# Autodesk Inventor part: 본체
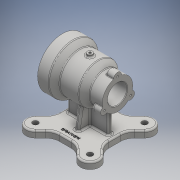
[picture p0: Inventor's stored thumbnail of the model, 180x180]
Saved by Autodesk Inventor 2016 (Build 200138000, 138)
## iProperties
Created: 2017-03
Part Number: 본체
Material: 일반
Document SubType Name: Modeling
Designer: USER
Density: 1 g/cm^3
Appearance: 기본값
Author: USER
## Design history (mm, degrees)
sketch "스케치1"
  geometry: L1 (0, 0)-(-100, 0); L2 (0, 35)-(-23, 35); L3 (-23, 35)-(-23, 26); L4 (-23, 26)-(-70, 26); L5 (-70, 26)-(-70, 17.5); L6 (-70, 17.5)-(-100, 17.5); L7 (-100, 17.5)-(-100, 27.5); L8 (-100, 27.5)-(-77, 27.5); L9 (-77, 27.5)-(-65, 36); L10 (-65, 36)-(-31, 36); L11 (-31, 36)-(-20, 45); L12 (-20, 45)-(0, 45); L13 (0, 45)-(0, 35); 2 further points
  constraints: 26 end point, 7 perpendicular, 2 horizontal, 2 midpoint, 2 parallel, 2 vertical alignment
  dimensions: "d0" = 35 diameter of L6 L1; "d1" = 100 distance between parallel lines of L7 L13; "d2" = 52 diameter of L4 L1; "d3" = 70 diameter of L2 L1; "d4" = 90 diameter of L12 L1; "d5" = 55 diameter of L8 L1; "d6" = 72 diameter of L10 L1; "d7" = 23 distance of L2.start L2.end; "d8" = 47 distance of L3.end L4.end; "d9" = 20 distance of L11.end L12.end; "d11" = 31 horizontal distance of L10.end L12.end; "d12" = 65 distance from line of L9.end L13; "d13" = 23 distance of L7.end L8.end
revolve "회전1" sketch "스케치1" stored, may be unused: angle "d14" = 90 deg
node "작업 평면1"
sketch "스케치2" dims "d26" = 140
  geometry: L1 (5, 45)-(95, 45); L2 (95, 45)-(95, -45); L3 (95, -45)-(5, -45); L4 (5, -45)-(5, 45); L5 (100, 27.5)-(100, -27.5) reference; L6 (50, 45)-(50, -45); L7 (29.042, 45)-(12.523, 61.518); L8 (5, 20.958)-(-11.518, 37.477); L9 (0.503, 49.497)-(99.487, -49.487); L10 (99.073, 49.073)-(0.078, -49.922); A1 r 17 centre (0.503, 49.497) between (12.523, 61.518) and (-11.518, 37.477); 5 further points
  constraints: 18 end point, 6 point on line, 4 midpoint, 2 coincident, 2 horizontal alignment, 2 parallel, 2 point on circle, 1 centre point, 1 horizontal, 1 perpendicular, 1 tangent, 1 vertical alignment, 4 other
  dimensions: "d16" = 90 distance of L1.start L1.end; "d17" = 90 distance of L1.end L2.end; "d18" = 50 distance from line of L6 point (0, 0); "d21" = 34 distance between parallel lines of L8 L7
extrude "돌출1" join sketch "스케치2" distance "d28" = 12; taper "d29" = 0 deg
extrude "돌출2" join sketch "스케치2" distance "d30" = 12; taper "d31" = 0 deg
node "작업 평면2"
sketch "스케치3"
  geometry: L1 (13, 4)-(87, 4); L2 (87, 4)-(87, -4); L3 (87, -4)-(13, -4); L4 (13, -4)-(13, 4); 3 further points
  constraints: 8 end point, 2 parallel, 1 horizontal, 1 horizontal alignment, 1 midpoint, 1 perpendicular
  dimensions: "d33" = 8 distance of L3.end L1.start; "d34" = 37 distance from line of L4 point (50, 45); "d35" = 37 distance from line of L2 point (50, 45)
extrude "돌출3" join sketch "스케치3" stored distance "d36" = 0; taper "d37" = 0 deg
sketch "스케치4"
  geometry: L1 (-37.477, -70)-(-20.958, -70) reference; L2 (37.477, -70)-(20.958, -70) reference; L3 (0, 0)-(0, -58.122); L4 (-16.238, -20.306)-(-25, -70); L5 (16.238, -20.306)-(25, -70); L6 (-4, -70)-(-4, -44.822) reference; L7 (20.958, -70)-(-20.958, -70) reference; L8 (4, -70)-(4, -44.822) reference; A1 r 26 centre (0, 0) between (-16.238, -20.306) and (16.238, -20.306) reference; 1 further point
  constraints: 6 end point, 2 point on circle, 2 point on line, 1 vertical
  dimensions: "d40" = 25 distance from line of L4.end L3; "d41" = 25 horizontal distance of L3.end L5.end; "d42" = 100 deg angle of L2 L5; "d43" = 100 deg angle of L1 L4
feature "리브1" dims "d44" = 1, "d45" = 8, "d46" = 0, "d47" = 0, "d48" = 1, "d49" = 1
feature "리브2" dims "d50" = 1, "d51" = 8, "d52" = 0, "d53" = 0, "d54" = 1, "d55" = 1
sketch "스케치5"
  geometry: C1 r 5 at (0.503, 49.497); C2 r 5 at (99.497, 49.497); C3 r 5 at (99.497, -49.497); C4 r 5 at (0.503, -49.497); A1 r 17 centre (0.503, 49.497) between (12.523, 61.518) and (-11.518, 37.477) reference; A2 r 17 centre (99.497, 49.497) between (111.518, 37.477) and (87.477, 61.518) reference; A3 r 17 centre (99.497, -49.497) between (87.477, -61.518) and (111.518, -37.477) reference; A4 r 17 centre (0.503, -49.497) between (-11.518, -37.477) and (12.523, -61.518) reference; 1 further point
  constraints: 4 centre point, 3 concentric, 3 equal radius, 1 coincident
  dimensions: "d57" = 10 diameter of C1
extrude "돌출4" cut sketch "스케치5" stored distance "d58" = 0; taper "d59" = 0 deg
node "작업 평면4"
sketch "스케치6"
  geometry: L1 (0, 45)-(0, -45) reference; C1 r 5 at (50, 0); 1 further point
  constraints: 1 centre point, 1 horizontal alignment
  dimensions: "d62" = 10 diameter of C1; "d63" = 50 distance from line of L1 C1.centre
extrude "돌출5" join sketch "스케치6" stored distance "d64" = 15; taper "d65" = 0 deg
sketch "스케치7"
  geometry: C1 r 5 at (0, 0) reference; 2 further points
  constraints: 1 coincident
hole "구멍1" sketch "스케치7" at (0, 0) diameter "d66" = 4.134; stored, may be unused: countersink angle "d70" = 90 deg, drill point angle "d72" = 118 deg; dims "d67" = 10, "d68" = 4, "d69" = 2, "d71" = 14.2
sketch "스케치8"
  geometry: A1 r 27.5 centre (0, 0) between (-27.5, 0) and (-26.609, -6.943) reference; A2 r 7 centre (-27.5, 0) between (-26.609, 6.943) and (-26.609, -6.943); A3 r 27.5 centre (0, 0) between (27.208, 4) and (27.208, -4) reference; 2 further points
  constraints: 6 point on circle, 1 centre point, 1 coincident
  dimensions: "d73" = 7 radius of A2
extrude "돌출6" join sketch "스케치8" distance "d76" = 15; taper "d77" = 0 deg
fillet "모깎기1" dims "d78" = 3
fillet "모깎기2" dims "d79" = 1
sketch "스케치9"
  geometry: A1 r 7 centre (0, 0) between (0.127, 6.999) and (0.127, -6.999) reference; 2 further points
  constraints: 1 coincident
hole "구멍2" sketch "스케치9" at (0, 0) diameter "d83" = 3.242; stored, may be unused: countersink angle "d87" = 90 deg, drill point angle "d89" = 118 deg; dims "d84" = 9, "d85" = 4, "d86" = 2, "d88" = 11
sketch "스케치10" dims "d93" = 80
  geometry: 3 further points
  constraints: 2 horizontal alignment, 1 coincident, 2 other
hole "구멍3" sketch "스케치10" at (40, 0) diameter "d94" = 3.242; stored, may be unused: countersink angle "d98" = 90 deg, drill point angle "d100" = 118 deg; dims "d95" = 9, "d96" = 4, "d97" = 2, "d99" = 11
chamfer "모따기1" distance "d104" = 1; stored, may be unused: second distance "d105" = 2, angle "d106" = 45 deg
fillet "모깎기3" dims "d107" = 3
fillet "모깎기4" dims "d108" = 3
fillet "모깎기5" dims "d109" = 3
fillet "모깎기6" dims "d110" = 3
fillet "모깎기7" dims "d111" = 3
fillet "모깎기8" dims "d112" = 25
fillet "모깎기9" dims "d113" = 3
sketch "스케치11"
  geometry: L1 (95, -10.603)-(95, 10.603) reference; L2 (0, 0)-(121.979, 0); 1 further point
  constraints: 2 end point, 1 horizontal, 1 other
  dimensions: "d114" = 45 distance from line of L1 point (50, -35); "d116" = 35 distance from line of point (50, -35) L2
feature "엠보싱1" sketch "스케치11" dims "d0" = 35, "d1" = 100, "d2" = 52, "d3" = 70, "d4" = 90, "d5" = 55, "d6" = 72, "d7" = 23, "d8" = 47, "d9" = 20, "d11" = 31, "d12" = 65, "d13" = 23, "d16" = 90, "d17" = 90, "d18" = 50, "d21" = 34, "d26" = 140, "d117" = 0.5, "d118" = 0
node "솔리드1"
mirror "대칭1"
mirror "대칭2"
pattern_circular "원형 패턴1" dims "d81" = 360 deg
pattern_circular "원형 패턴2" dims angle "d91" = 360 deg
pattern_circular "원형 패턴3" dims angle "d102" = 360 deg
other parameters: "d15" = -82
